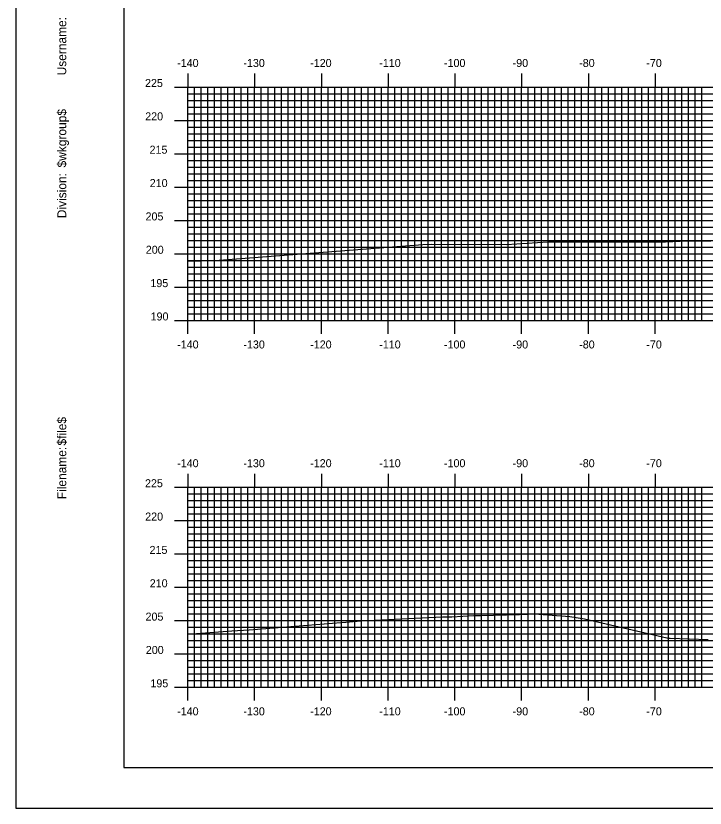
# Model space of a CAD drawing. Extents: x 852922 to 853266, y 364785 to 365005.
# Drawn here: x 852922.5 to 853025.7, y 364785.1 to 364903.9 of the extents above; entities that cross this region are included whole.
import ezdxf

# ---------------------------------------------------------------- set-up
doc = ezdxf.new("R2010")
doc.units = 0
for name, color, linetype in [('BORDER', 7, 'Continuous'), ('H_V ANNOTATION', 7, 'Continuous'), ('MAJOR', 7, 'Continuous'), ('MINOR', 7, 'Continuous'), ('PLOT BOUNDARY', 7, 'Continuous'), ('S_Roadway_Centerline', 7, 'Continuous')]:
    doc.layers.add(name, color=color, linetype=linetype)

msp = doc.modelspace()

# ---------------------------------------------------------------- linework, layer by layer
at = {"layer": 'BORDER'}
msp.add_lwpolyline([(852938.64, 364791.23), (853258.64, 364791.23), (853258.64, 365001.23), (852938.64, 365001.23)], close=True, dxfattribs=at)
at = {"layer": 'MAJOR'}
for p, q in [((852948.24, 364895.24), (852948.24, 364893.23)), ((852958.24, 364895.24), (852958.24, 364893.23)), ((852968.24, 364895.24), (852968.24, 364893.23)), ((852978.24, 364895.24), (852978.24, 364893.23)), ((852988.24, 364895.24), (852988.24, 364893.23)), ((852998.24, 364895.24), (852998.24, 364893.23)), ((853008.24, 364895.24), (853008.24, 364893.23)), ((853018.24, 364895.24), (853018.24, 364893.23)), ((852946.24, 364893.23), (852948.24, 364893.23)), ((852948.24, 364893.23), (853228.24, 364893.23)), ((852948.24, 364858.23), (852948.24, 364893.23)), ((852948.24, 364858.23), (852948.24, 364893.23)), ((852948.24, 364893.23), (853228.24, 364893.23)), ((852958.24, 364858.23), (852958.24, 364893.23)), ((852968.24, 364858.23), (852968.24, 364893.23)), ((852978.24, 364858.23), (852978.24, 364893.23)), ((852988.24, 364858.23), (852988.24, 364893.23)), ((852998.24, 364858.23), (852998.24, 364893.23)), ((853008.24, 364858.23), (853008.24, 364893.23)), ((853018.24, 364858.23), (853018.24, 364893.23)), ((852946.24, 364888.23), (852948.24, 364888.23)), ((852948.24, 364888.23), (853228.24, 364888.23)), ((852946.24, 364883.23), (852948.24, 364883.23)), ((852948.24, 364883.23), (853228.24, 364883.23)), ((852946.24, 364878.23), (852948.24, 364878.23)), ((852948.24, 364878.23), (853228.24, 364878.23)), ((852946.24, 364873.23), (852948.24, 364873.23)), ((852948.24, 364873.23), (853228.24, 364873.23)), ((852946.24, 364868.23), (852948.24, 364868.23)), ((852948.24, 364868.23), (853228.24, 364868.23)), ((852946.24, 364863.23), (852948.24, 364863.23)), ((852948.24, 364863.23), (853228.24, 364863.23)), ((852946.24, 364858.23), (852948.24, 364858.23)), ((852948.24, 364858.23), (853228.24, 364858.23)), ((852948.24, 364858.23), (853228.24, 364858.23)), ((852948.24, 364856.23), (852948.24, 364858.23)), ((852958.24, 364856.23), (852958.24, 364858.23)), ((852968.24, 364856.23), (852968.24, 364858.23)), ((852978.24, 364856.23), (852978.24, 364858.23)), ((852988.24, 364856.23), (852988.24, 364858.23)), ((852998.24, 364856.23), (852998.24, 364858.23)), ((853008.24, 364856.23), (853008.24, 364858.23)), ((853018.24, 364856.23), (853018.24, 364858.23)), ((852948.24, 364835.24), (852948.24, 364833.23)), ((852958.24, 364835.24), (852958.24, 364833.23)), ((852968.24, 364835.24), (852968.24, 364833.23)), ((852978.24, 364835.24), (852978.24, 364833.23)), ((852988.24, 364835.24), (852988.24, 364833.23)), ((852998.24, 364835.24), (852998.24, 364833.23)), ((853008.24, 364835.24), (853008.24, 364833.23)), ((853018.24, 364835.24), (853018.24, 364833.23)), ((852946.24, 364833.23), (852948.24, 364833.23)), ((852948.24, 364833.23), (853228.24, 364833.23)), ((852948.24, 364803.23), (852948.24, 364833.23)), ((852948.24, 364803.23), (852948.24, 364833.23)), ((852948.24, 364833.23), (853228.24, 364833.23)), ((852958.24, 364803.23), (852958.24, 364833.23)), ((852968.24, 364803.23), (852968.24, 364833.23)), ((852978.24, 364803.23), (852978.24, 364833.23)), ((852988.24, 364803.23), (852988.24, 364833.23)), ((852998.24, 364803.23), (852998.24, 364833.23)), ((853008.24, 364803.23), (853008.24, 364833.23)), ((853018.24, 364803.23), (853018.24, 364833.23)), ((852946.24, 364828.23), (852948.24, 364828.23)), ((852948.24, 364828.23), (853228.24, 364828.23)), ((852946.24, 364823.23), (852948.24, 364823.23)), ((852948.24, 364823.23), (853228.24, 364823.23)), ((852946.24, 364818.23), (852948.24, 364818.23)), ((852948.24, 364818.23), (853228.24, 364818.23)), ((852946.24, 364813.23), (852948.24, 364813.23)), ((852948.24, 364813.23), (853228.24, 364813.23)), ((852946.24, 364808.23), (852948.24, 364808.23)), ((852948.24, 364808.23), (853228.24, 364808.23)), ((852946.24, 364803.23), (852948.24, 364803.23)), ((852948.24, 364803.23), (853228.24, 364803.23)), ((852948.24, 364803.23), (853228.24, 364803.23)), ((852948.24, 364801.23), (852948.24, 364803.23)), ((852958.24, 364801.23), (852958.24, 364803.23)), ((852968.24, 364801.23), (852968.24, 364803.23)), ((852978.24, 364801.23), (852978.24, 364803.23)), ((852988.24, 364801.23), (852988.24, 364803.23)), ((852998.24, 364801.23), (852998.24, 364803.23)), ((853008.24, 364801.23), (853008.24, 364803.23)), ((853018.24, 364801.23), (853018.24, 364803.23))]:
    msp.add_line(p, q, dxfattribs=at)
at = {"layer": 'MINOR'}
for p, q in [((852948.24, 364858.23), (852948.24, 364893.23)), ((852949.24, 364858.23), (852949.24, 364893.23)), ((852950.24, 364858.23), (852950.24, 364893.23)), ((852951.24, 364858.23), (852951.24, 364893.23)), ((852952.24, 364858.23), (852952.24, 364893.23)), ((852953.24, 364858.23), (852953.24, 364893.23)), ((852954.24, 364858.23), (852954.24, 364893.23)), ((852955.24, 364858.23), (852955.24, 364893.23)), ((852956.24, 364858.23), (852956.24, 364893.23)), ((852957.24, 364858.23), (852957.24, 364893.23)), ((852959.24, 364858.23), (852959.24, 364893.23)), ((852960.24, 364858.23), (852960.24, 364893.23)), ((852961.24, 364858.23), (852961.24, 364893.23)), ((852962.24, 364858.23), (852962.24, 364893.23)), ((852963.24, 364858.23), (852963.24, 364893.23)), ((852964.24, 364858.23), (852964.24, 364893.23)), ((852965.24, 364858.23), (852965.24, 364893.23)), ((852966.24, 364858.23), (852966.24, 364893.23)), ((852967.24, 364858.23), (852967.24, 364893.23)), ((852969.24, 364858.23), (852969.24, 364893.23)), ((852970.24, 364858.23), (852970.24, 364893.23)), ((852971.24, 364858.23), (852971.24, 364893.23)), ((852972.24, 364858.23), (852972.24, 364893.23)), ((852973.24, 364858.23), (852973.24, 364893.23)), ((852974.24, 364858.23), (852974.24, 364893.23)), ((852975.24, 364858.23), (852975.24, 364893.23)), ((852976.24, 364858.23), (852976.24, 364893.23)), ((852977.24, 364858.23), (852977.24, 364893.23)), ((852979.24, 364858.23), (852979.24, 364893.23)), ((852980.24, 364858.23), (852980.24, 364893.23)), ((852981.24, 364858.23), (852981.24, 364893.23)), ((852982.24, 364858.23), (852982.24, 364893.23)), ((852983.24, 364858.23), (852983.24, 364893.23)), ((852984.24, 364858.23), (852984.24, 364893.23)), ((852985.24, 364858.23), (852985.24, 364893.23)), ((852986.24, 364858.23), (852986.24, 364893.23)), ((852987.24, 364858.23), (852987.24, 364893.23)), ((852989.24, 364858.23), (852989.24, 364893.23)), ((852990.24, 364858.23), (852990.24, 364893.23)), ((852991.24, 364858.23), (852991.24, 364893.23)), ((852992.24, 364858.23), (852992.24, 364893.23)), ((852993.24, 364858.23), (852993.24, 364893.23)), ((852994.24, 364858.23), (852994.24, 364893.23)), ((852995.24, 364858.23), (852995.24, 364893.23)), ((852996.24, 364858.23), (852996.24, 364893.23)), ((852997.24, 364858.23), (852997.24, 364893.23)), ((852999.24, 364858.23), (852999.24, 364893.23)), ((853000.24, 364858.23), (853000.24, 364893.23)), ((853001.24, 364858.23), (853001.24, 364893.23)), ((853002.24, 364858.23), (853002.24, 364893.23)), ((853003.24, 364858.23), (853003.24, 364893.23)), ((853004.24, 364858.23), (853004.24, 364893.23)), ((853005.24, 364858.23), (853005.24, 364893.23)), ((853006.24, 364858.23), (853006.24, 364893.23)), ((853007.24, 364858.23), (853007.24, 364893.23)), ((853009.24, 364858.23), (853009.24, 364893.23)), ((853010.24, 364858.23), (853010.24, 364893.23)), ((853011.24, 364858.23), (853011.24, 364893.23)), ((853012.24, 364858.23), (853012.24, 364893.23)), ((853013.24, 364858.23), (853013.24, 364893.23)), ((853014.24, 364858.23), (853014.24, 364893.23)), ((853015.24, 364858.23), (853015.24, 364893.23)), ((853016.24, 364858.23), (853016.24, 364893.23)), ((853017.24, 364858.23), (853017.24, 364893.23)), ((853019.24, 364858.23), (853019.24, 364893.23)), ((853020.24, 364858.23), (853020.24, 364893.23)), ((853021.24, 364858.23), (853021.24, 364893.23)), ((853022.24, 364858.23), (853022.24, 364893.23)), ((853023.24, 364858.23), (853023.24, 364893.23)), ((853024.24, 364858.23), (853024.24, 364893.23)), ((853025.24, 364858.23), (853025.24, 364893.23)), ((852948.24, 364892.23), (853228.24, 364892.23)), ((852948.24, 364892.23), (852950.25, 364892.23)), ((852948.24, 364891.23), (853228.24, 364891.23)), ((852948.24, 364891.23), (852950.25, 364891.23)), ((852948.24, 364890.23), (853228.24, 364890.23)), ((852948.24, 364890.23), (852950.25, 364890.23)), ((852948.24, 364889.23), (853228.24, 364889.23)), ((852948.24, 364889.23), (852950.25, 364889.23)), ((852948.24, 364887.23), (853228.24, 364887.23)), ((852948.24, 364887.23), (852950.25, 364887.23)), ((852948.24, 364886.23), (853228.24, 364886.23)), ((852948.24, 364886.23), (852950.25, 364886.23)), ((852948.24, 364885.23), (853228.24, 364885.23)), ((852948.24, 364885.23), (852950.25, 364885.23)), ((852948.24, 364884.23), (853228.24, 364884.23)), ((852948.24, 364884.23), (852950.25, 364884.23)), ((852948.24, 364882.23), (853228.24, 364882.23)), ((852948.24, 364882.23), (852950.25, 364882.23)), ((852948.24, 364881.23), (853228.24, 364881.23)), ((852948.24, 364881.23), (852950.25, 364881.23)), ((852948.24, 364880.23), (853228.24, 364880.23)), ((852948.24, 364880.23), (852950.25, 364880.23)), ((852948.24, 364879.23), (853228.24, 364879.23)), ((852948.24, 364879.23), (852950.25, 364879.23)), ((852948.24, 364877.23), (853228.24, 364877.23)), ((852948.24, 364877.23), (852950.25, 364877.23)), ((852948.24, 364876.23), (853228.24, 364876.23)), ((852948.24, 364876.23), (852950.25, 364876.23)), ((852948.24, 364875.23), (853228.24, 364875.23)), ((852948.24, 364875.23), (852950.25, 364875.23)), ((852948.24, 364874.23), (853228.24, 364874.23)), ((852948.24, 364874.23), (852950.25, 364874.23)), ((852948.24, 364872.23), (853228.24, 364872.23)), ((852948.24, 364872.23), (852950.25, 364872.23)), ((852948.24, 364871.23), (853228.24, 364871.23)), ((852948.24, 364871.23), (852950.25, 364871.23)), ((852948.24, 364870.23), (853228.24, 364870.23)), ((852948.24, 364870.23), (852950.25, 364870.23)), ((852948.24, 364869.23), (853228.24, 364869.23)), ((852948.24, 364869.23), (852950.25, 364869.23)), ((852948.24, 364867.23), (853228.24, 364867.23)), ((852948.24, 364867.23), (852950.25, 364867.23)), ((852948.24, 364866.23), (853228.24, 364866.23)), ((852948.24, 364866.23), (852950.25, 364866.23)), ((852948.24, 364865.23), (853228.24, 364865.23)), ((852948.24, 364865.23), (852950.25, 364865.23)), ((852948.24, 364864.23), (853228.24, 364864.23)), ((852948.24, 364864.23), (852950.25, 364864.23)), ((852948.24, 364862.23), (853228.24, 364862.23)), ((852948.24, 364862.23), (852950.25, 364862.23)), ((852948.24, 364861.23), (853228.24, 364861.23)), ((852948.24, 364861.23), (852950.25, 364861.23)), ((852948.24, 364860.23), (853228.24, 364860.23)), ((852948.24, 364860.23), (852950.25, 364860.23)), ((852948.24, 364859.23), (853228.24, 364859.23)), ((852948.24, 364859.23), (852950.25, 364859.23)), ((852949.24, 364803.23), (852949.24, 364833.23)), ((852950.24, 364803.23), (852950.24, 364833.23)), ((852951.24, 364803.23), (852951.24, 364833.23)), ((852952.24, 364803.23), (852952.24, 364833.23)), ((852953.24, 364803.23), (852953.24, 364833.23)), ((852954.24, 364803.23), (852954.24, 364833.23)), ((852955.24, 364803.23), (852955.24, 364833.23)), ((852956.24, 364803.23), (852956.24, 364833.23)), ((852957.24, 364803.23), (852957.24, 364833.23)), ((852959.24, 364803.23), (852959.24, 364833.23)), ((852960.24, 364803.23), (852960.24, 364833.23)), ((852961.24, 364803.23), (852961.24, 364833.23)), ((852962.24, 364803.23), (852962.24, 364833.23)), ((852963.24, 364803.23), (852963.24, 364833.23)), ((852964.24, 364803.23), (852964.24, 364833.23)), ((852965.24, 364803.23), (852965.24, 364833.23)), ((852966.24, 364803.23), (852966.24, 364833.23)), ((852967.24, 364803.23), (852967.24, 364833.23)), ((852969.24, 364803.23), (852969.24, 364833.23)), ((852970.24, 364803.23), (852970.24, 364833.23)), ((852971.24, 364803.23), (852971.24, 364833.23)), ((852972.24, 364803.23), (852972.24, 364833.23)), ((852973.24, 364803.23), (852973.24, 364833.23)), ((852974.24, 364803.23), (852974.24, 364833.23)), ((852975.24, 364803.23), (852975.24, 364833.23)), ((852976.24, 364803.23), (852976.24, 364833.23)), ((852977.24, 364803.23), (852977.24, 364833.23)), ((852979.24, 364803.23), (852979.24, 364833.23)), ((852980.24, 364803.23), (852980.24, 364833.23)), ((852981.24, 364803.23), (852981.24, 364833.23)), ((852982.24, 364803.23), (852982.24, 364833.23)), ((852983.24, 364803.23), (852983.24, 364833.23)), ((852984.24, 364803.23), (852984.24, 364833.23)), ((852985.24, 364803.23), (852985.24, 364833.23)), ((852986.24, 364803.23), (852986.24, 364833.23)), ((852987.24, 364803.23), (852987.24, 364833.23)), ((852989.24, 364803.23), (852989.24, 364833.23)), ((852990.24, 364803.23), (852990.24, 364833.23)), ((852991.24, 364803.23), (852991.24, 364833.23)), ((852992.24, 364803.23), (852992.24, 364833.23)), ((852993.24, 364803.23), (852993.24, 364833.23)), ((852994.24, 364803.23), (852994.24, 364833.23)), ((852995.24, 364803.23), (852995.24, 364833.23)), ((852996.24, 364803.23), (852996.24, 364833.23)), ((852997.24, 364803.23), (852997.24, 364833.23)), ((852999.24, 364803.23), (852999.24, 364833.23)), ((853000.24, 364803.23), (853000.24, 364833.23)), ((853001.24, 364803.23), (853001.24, 364833.23)), ((853002.24, 364803.23), (853002.24, 364833.23)), ((853003.24, 364803.23), (853003.24, 364833.23)), ((853004.24, 364803.23), (853004.24, 364833.23)), ((853005.24, 364803.23), (853005.24, 364833.23)), ((853006.24, 364803.23), (853006.24, 364833.23)), ((853007.24, 364803.23), (853007.24, 364833.23)), ((853009.24, 364803.23), (853009.24, 364833.23)), ((853010.24, 364803.23), (853010.24, 364833.23)), ((853011.24, 364803.23), (853011.24, 364833.23)), ((853012.24, 364803.23), (853012.24, 364833.23)), ((853013.24, 364803.23), (853013.24, 364833.23)), ((853014.24, 364803.23), (853014.24, 364833.23)), ((853015.24, 364803.23), (853015.24, 364833.23)), ((853016.24, 364803.23), (853016.24, 364833.23)), ((853017.24, 364803.23), (853017.24, 364833.23)), ((853019.24, 364803.23), (853019.24, 364833.23)), ((853020.24, 364803.23), (853020.24, 364833.23)), ((853021.24, 364803.23), (853021.24, 364833.23)), ((853022.24, 364803.23), (853022.24, 364833.23)), ((853023.24, 364803.23), (853023.24, 364833.23)), ((853024.24, 364803.23), (853024.24, 364833.23)), ((853025.24, 364803.23), (853025.24, 364833.23)), ((852948.24, 364832.23), (853228.24, 364832.23)), ((852948.24, 364832.23), (852950.25, 364832.23)), ((852948.24, 364831.23), (853228.24, 364831.23)), ((852948.24, 364831.23), (852950.25, 364831.23)), ((852948.24, 364830.23), (853228.24, 364830.23)), ((852948.24, 364830.23), (852950.25, 364830.23)), ((852948.24, 364829.23), (853228.24, 364829.23)), ((852948.24, 364829.23), (852950.25, 364829.23)), ((852948.24, 364827.23), (853228.24, 364827.23)), ((852948.24, 364827.23), (852950.25, 364827.23)), ((852948.24, 364826.23), (853228.24, 364826.23)), ((852948.24, 364826.23), (852950.25, 364826.23)), ((852948.24, 364825.23), (853228.24, 364825.23)), ((852948.24, 364825.23), (852950.25, 364825.23)), ((852948.24, 364824.23), (853228.24, 364824.23)), ((852948.24, 364824.23), (852950.25, 364824.23)), ((852948.24, 364822.23), (853228.24, 364822.23)), ((852948.24, 364822.23), (852950.25, 364822.23)), ((852948.24, 364821.23), (853228.24, 364821.23)), ((852948.24, 364821.23), (852950.25, 364821.23)), ((852948.24, 364820.23), (853228.24, 364820.23)), ((852948.24, 364820.23), (852950.25, 364820.23)), ((852948.24, 364819.23), (853228.24, 364819.23)), ((852948.24, 364819.23), (852950.25, 364819.23)), ((852948.24, 364817.23), (853228.24, 364817.23)), ((852948.24, 364817.23), (852950.25, 364817.23)), ((852948.24, 364816.23), (853228.24, 364816.23)), ((852948.24, 364816.23), (852950.25, 364816.23)), ((852948.24, 364815.23), (853228.24, 364815.23)), ((852948.24, 364815.23), (852950.25, 364815.23)), ((852948.24, 364814.23), (853228.24, 364814.23)), ((852948.24, 364814.23), (852950.25, 364814.23)), ((852948.24, 364812.23), (853228.24, 364812.23)), ((852948.24, 364812.23), (852950.25, 364812.23)), ((852948.24, 364811.23), (853228.24, 364811.23)), ((852948.24, 364811.23), (852950.25, 364811.23)), ((852948.24, 364810.23), (853228.24, 364810.23)), ((852948.24, 364810.23), (852950.25, 364810.23)), ((852948.24, 364809.23), (853228.24, 364809.23)), ((852948.24, 364809.23), (852950.25, 364809.23)), ((852948.24, 364807.23), (853228.24, 364807.23)), ((852948.24, 364807.23), (852950.25, 364807.23)), ((852948.24, 364806.23), (853228.24, 364806.23)), ((852948.24, 364806.23), (852950.25, 364806.23)), ((852948.24, 364805.23), (853228.24, 364805.23)), ((852948.24, 364805.23), (852950.25, 364805.23)), ((852948.24, 364804.23), (853228.24, 364804.23)), ((852948.24, 364804.23), (852950.25, 364804.23))]:
    msp.add_line(p, q, dxfattribs=at)
at = {"layer": 'PLOT BOUNDARY'}
msp.add_lwpolyline([(852922.46, 364785.11), (853262.46, 364785.11), (853262.46, 365005.11), (852922.46, 365005.11)], close=True, dxfattribs=at)
at = {"layer": 'S_Roadway_Centerline'}
for points in [[(852948.24, 364867.11), (852952.29, 364867.22), (852982.81, 364869.57), (852983.43, 364869.61), (852984.76, 364869.67), (852995.96, 364869.61), (853002.18, 364870.03), (853019.78, 364870.03), (853022, 364870.13), (853031.21, 364870.21), (853040.95, 364870.27), (853047.09, 364870.61), (853061.47, 364871.31), (853080.2, 364872.29), (853086.66, 364872.73), (853095.62, 364874.31), (853108.71, 364876.76), (853119.92, 364878.67), (853126.68, 364878.29), (853138.55, 364878.41), (853139.24, 364878.44), (853141.36, 364878.39), (853158.49, 364878.3)], [(852948.24, 364811.2), (852954.81, 364811.68), (852957.41, 364811.87), (852971.15, 364812.95), (852971.9, 364812.99), (852974.15, 364813.19), (852986.41, 364813.78), (852987.79, 364813.81), (852991.07, 364814), (852992.1, 364814), (852997.95, 364814.17), (853000.59, 364814.23), (853000.83, 364814.21), (853005.48, 364813.87), (853007.66, 364813.51), (853019.98, 364810.66), (853020.15, 364810.62), (853020.29, 364810.6), (853020.51, 364810.6), (853026.18, 364810.39)]]:
    msp.add_lwpolyline(points, dxfattribs=at)

# ---------------------------------------------------------------- texts
at = {"layer": 'BORDER'}
for s, p in [('Username:', (852930.01, 364894.97)), ('$wkgroup$', (852930.01, 364881.17)), ('Division:', (852930.01, 364873.56)), ('$file$', (852930.01, 364839.48)), ('Filename:', (852930.01, 364831.43))]:
    msp.add_text(s, height=1.339, rotation=90, dxfattribs=at).set_placement(p)
at = {"layer": 'H_V ANNOTATION'}
for s, p in [('-140', (852946.63, 364896.23)), ('-130', (852956.55, 364896.23)), ('-120', (852966.56, 364896.23)), ('-110', (852976.91, 364896.23)), ('-100', (852986.61, 364896.23)), ('-90', (852996.9, 364896.23)), ('-80', (853006.87, 364896.23)), ('-70', (853016.93, 364896.23)), ('225', (852941.81, 364893.23)), ('220', (852941.84, 364888.23)), ('215', (852942.49, 364883.23)), ('210', (852942.52, 364878.23)), ('205', (852941.89, 364873.23)), ('200', (852941.93, 364868.23)), ('195', (852942.62, 364863.23)), ('190', (852942.65, 364858.23)), ('-140', (852946.63, 364854.03)), ('-130', (852956.55, 364854.03)), ('-120', (852966.56, 364854.03)), ('-110', (852976.91, 364854.03)), ('-100', (852986.61, 364854.03)), ('-90', (852996.9, 364854.03)), ('-80', (853006.87, 364854.03)), ('-70', (853016.93, 364854.03)), ('-140', (852946.63, 364836.23)), ('-130', (852956.55, 364836.23)), ('-120', (852966.56, 364836.23)), ('-110', (852976.91, 364836.23)), ('-100', (852986.61, 364836.23)), ('-90', (852996.9, 364836.23)), ('-80', (853006.87, 364836.23)), ('-70', (853016.93, 364836.23)), ('225', (852941.81, 364833.23)), ('220', (852941.84, 364828.23)), ('215', (852942.49, 364823.23)), ('210', (852942.52, 364818.23)), ('205', (852941.89, 364813.23)), ('200', (852941.93, 364808.23)), ('195', (852942.62, 364803.23)), ('-140', (852946.63, 364799.03)), ('-130', (852956.55, 364799.03)), ('-120', (852966.56, 364799.03)), ('-110', (852976.91, 364799.03)), ('-100', (852986.61, 364799.03)), ('-90', (852996.9, 364799.03)), ('-80', (853006.87, 364799.03)), ('-70', (853016.93, 364799.03))]:
    msp.add_text(s, height=1.2, dxfattribs=at).set_placement(p)
at = {"layer": 'MAJOR'}
for p in [(852948.23, 364858.23), (852948.23, 364803.23)]:
    msp.add_text('-', height=0.012, dxfattribs=at).set_placement(p)
at = {"layer": 'S_Roadway_Centerline'}
for s, p in [('C', (852974.15, 364813.19)), ('L', (852974.15, 364813.18))]:
    msp.add_text(s, height=0.0146, dxfattribs=at).set_placement(p)

doc.saveas('drawing.dxf')
